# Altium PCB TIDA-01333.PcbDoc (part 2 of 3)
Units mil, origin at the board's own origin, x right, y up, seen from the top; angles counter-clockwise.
Board outline 6250 x 2150 mil, 4 copper layers (Top Layer, GND, VDD, Bottom Layer), stack 61.6 mil thick; 242 components, 144 nets, 711 pads, 252 vias.
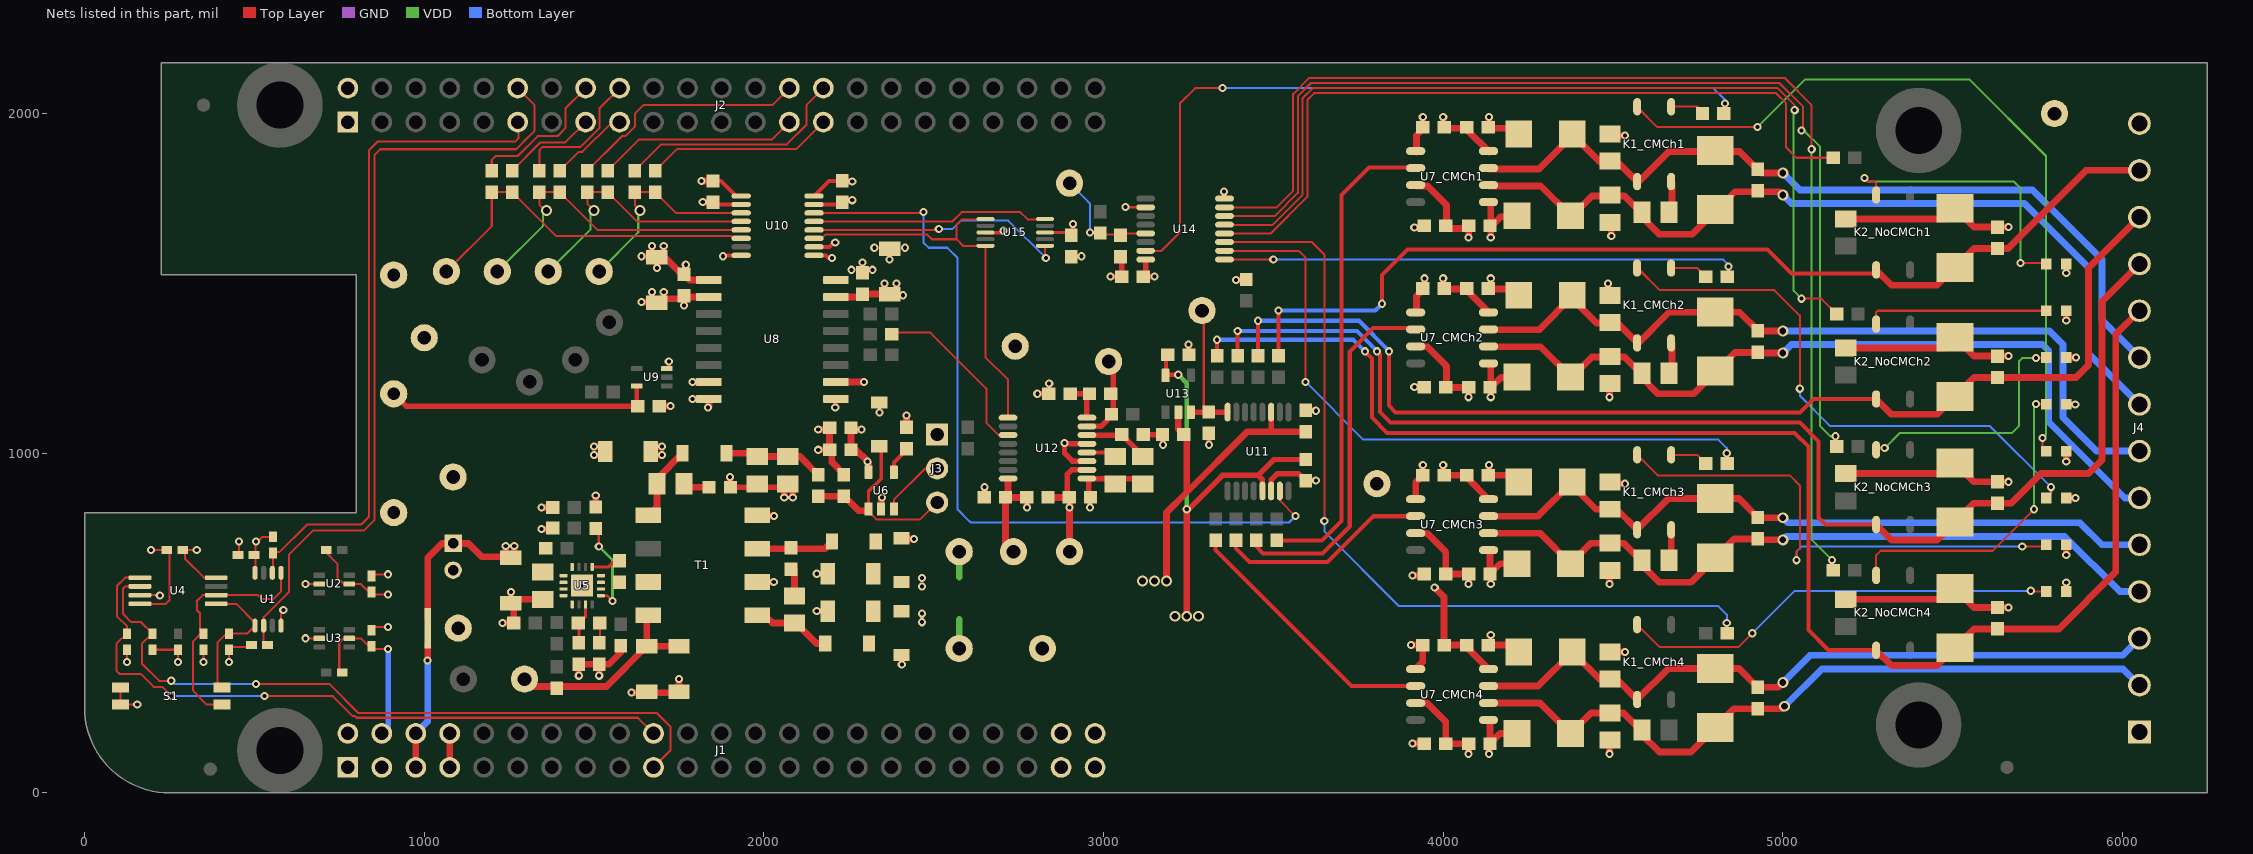
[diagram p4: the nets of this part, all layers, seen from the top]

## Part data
C1 C2 C3 C4: "CAP, CERM, 0.1 µF, 50 V, +/- 10%, X7R, 0402"
C5: "CAP, CERM, 1000 pF, 2000 V, +/- 10%, X7R, 1206_190"
C6: "CAP, AL, 47 µF, 35 V, +/- 20%, TH"
C7 C13 C14 C33 C36: "CAP, CERM, 22 µF, 10 V, +/- 10%, X7R, 1206"
C8 C18 C19 C49 C50: "CAP, CERM, 10 µF, 10 V, +/- 10%, X7R, 0805"
C9 C12: "CAP, CERM, 2.2 µF, 50 V, +/- 10%, X7R, 1206"
C10 C17 C25_CMCh1 C25_CMCh2 C25_CMCh3 C25_CMCh4 C30_CMCh1 C30_CMCh2 C30_CMCh3 C30_CMCh4 C34 C35 C37 C38 C39 C40 C43 C46 C47 C51 C52 C53: "CAP, CERM, 0.1 µF, 50 V, +/- 10%, X7R, 0603"
C11 C23: "CAP, CERM, 15 pF, 50 V, +/- 5%, C0G/NP0, 0603"
C15 C16 C21: "CAP, CERM, 2.2 µF, 10 V, +/- 10%, X7R, 0603"
C20: "CAP, CERM, 0.033 µF, 50 V, +/- 10%, X7R, 0603"
C22: "CAP, CERM, 82 pF, 50 V, +/- 5%, C0G/NP0, 0603"
C24 C28_CMCh1 C28_CMCh2 C28_CMCh3 C28_CMCh4 C32_NoCMCh1 C32_NoCMCh2 C32_NoCMCh3 C32_NoCMCh4: "CAP, CERM, 0.01 µF, 100 V, +/- 10%, X7R, 0603"
C26_CMCh1 C26_CMCh2 C26_CMCh3 C26_CMCh4 C31_CMCh1 C31_CMCh2 C31_CMCh3 C31_CMCh4 C41 C42 C48: "CAP, CERM, 1 µF, 16 V, +/- 10%, X7R, 0603"
C27_CMCh1 C27_CMCh2 C27_CMCh3 C27_CMCh4 C29_CMCh1 C29_CMCh2 C29_CMCh3 C29_CMCh4: "CAP, CERM, 1000 pF, 630 V, +/- 5%, X7R, 0805"
C44: "CAP, CERM, 100 pF, 50 V, +/- 5%, C0G/NP0, 0603"
C45: "CAP, CERM, 820 pF, 50 V, +/- 5%, C0G/NP0, 0603"
D1 D4: "Diode, Schottky, 100 V, 0.2 A, SOD-123"
D2 D3: "Diode, Zener, 16 V, 500 mW, SOD-123"
D5 D6: "Diode, Schottky, 30 V, 0.5 A, SOD-123"
D7_CMCh1 D7_CMCh2 D7_CMCh3 D7_CMCh4 D10_CMCh1 D10_CMCh2 D10_CMCh3 D10_CMCh4: "Diode, TVS, Bi, 160 V, 400 W, SMA"
D8_CMCh1 D8_CMCh2 D8_CMCh3 D8_CMCh4 D11_NoCMCh1 D11_NoCMCh2 D11_NoCMCh3 D11_NoCMCh4: "LED, Blue, SMD"
D9_CMCh1 D9_CMCh2 D9_CMCh3 D9_CMCh4 D12_NoCMCh1 D12_NoCMCh2 D12_NoCMCh3 D12_NoCMCh4: "Diode, TVS, Bi, 36 V, 600 W, SMB"
FID1 FID2 FID3: "Fiducial mark.  There is nothing to buy or mount."
J1 J2: "Female Connector, 2.54mm, 23x2, TH"
J3: "Header, 100mil, 3x1, Tin, TH"
J4: "Header (Shrouded), 3.5mm, 14x1, Tin, R/A, TH"
K1_CMCh1 K1_CMCh2 K1_CMCh3 K1_CMCh4 K2_NoCMCh1 K2_NoCMCh2 K2_NoCMCh3 K2_NoCMCh4: "Relay, SPST-NO (1 Form A), 0.1 A, 1.2 VDC, SMD"
Logo1: library part Pb-Free
Logo2: library part FCC_disclaimer, "FCC_disclaimer"
MH1 MH2 MH3 MH4: library part "Mounting Hole (Imperial) with Pads", "PCB Mounting Hole"
NT1: "Single point connection between nets."
R1 R2 R3 R4 R13 R14 R15: "RES, 47 k, 5%, 0.063 W, 0402"
R5 R6 R7 R8 R9 R10 R11 R12 R25 R38 R46: "RES, 0, 5%, 0.1 W, 0603"
R16 R17: "RES, 6.65 k, 1%, 0.063 W, 0402"
R18 R27: "RES, 1.0 k, 5%, 0.125 W, 0805"
R19 R28: "RES, 10 k, 5%, 0.1 W, 0603"
R20: "RES, 220 k, 5%, 0.1 W, 0603"
R21: "RES, 16.2 k, 1%, 0.1 W, 0603"
R22 R33 R34 R35 R36 R49: "RES, 49.9, 1%, 0.1 W, 0603"
R23: "RES, 75 k, 5%, 0.1 W, 0603"
R24: "RES, 10.0 k, 1%, 0.1 W, 0603"
R26: "RES, 240 k, 5%, 0.1 W, 0603"
R29_CMCh1 R29_CMCh2 R29_CMCh3 R29_CMCh4 R31_NoCMCh1 R31_NoCMCh2 R31_NoCMCh3 R31_NoCMCh4: "RES, 180, 5%, 0.1 W, 0603"
R30_CMCh1 R30_CMCh2 R30_CMCh3 R30_CMCh4 R32_NoCMCh1 R32_NoCMCh2 R32_NoCMCh3 R32_NoCMCh4: "RES, 200, 0.1%, 0.125 W, 0805"
R37 R39 R40 R41 R42 R43 R44 R45: "RES, 5.11 k, 1%, 0.1 W, 0603"
R47: "RES, 374, 1%, 0.1 W, 0603"
R48: "RES, 100 k, 5%, 0.1 W, 0603"
R50: "RES, 47 k, 5%, 0.1 W, 0603"
S1: "Switch, SPST, Off-On, 2 Pos, SMD"
SH-J1: "Shunt, 2.54mm, Gold, Black"
T1: "Transformer, 2.7 uH, SMT"
TP1 TP2 TP3: "TEST POINT.  No entry in BOM."
TP4 TP5 TP7 TP10: "Test Point, Miniature, Red, TH"
TP6 TP11 TP12 TP13 TP14 TP26: "Test Point, Miniature, Black, TH"
TP8: "Test Point, Miniature, White, TH"
TP9 TP15 TP16 TP17 TP18 TP19 TP20 TP21 TP22 TP24 TP25 TP27: "Test Point, Miniature, Yellow, TH"
TP23: "Test Point, Miniature, Orange, TH"
U1: "Dual 2-Input Exclusive-OR Gate, DCT0008A"
U2 U3: "Single 3-Input Positive-OR Gate, DCK0006A"
U4: "256K I2C CMOS Serial EEPROM, TSSOP-8"
U5: "2.95V To 6V Input, 2W, Isolated DC/DC Converter with Integrated FETs, RTE0016F (WQFN-16)"
U6: "150-mA Low-noise Low-dropout Regulator With Shutdown, DBV0005A"
U7_CMCh1 U7_CMCh2 U7_CMCh3 U7_CMCh4: "High Common-Mode Voltage Difference Amplifier, D0008A"
U8: "ISOW7841DW, DW0016B"
U9: "Single Power Supply Single Buffer Gate with 3-State Output CMOS Logic Level Shifter, DCK0005A"
U10: "4242-VPK Small-Footprint and Low-Power Quad Channels Digital Isolators, DBQ0016A"
U11: "MUX36xxx 36-V, Low-Capacitance, Low-Leakage-Current, Precision, Analog Multiplexers, PW0016A (TSSOP-16)"
U12: "16-bit, 1 MSPS, 5V SAR ADC with Integrated Analog Front End & Bipolar Inputs, PW0016A (TSSOP-16)"
U13: "36-V, Precision, Rail-to-Rail Input/Output, Low Offset Voltage, Low Input Bias Current Op Amp with e-trim, DBV0005A"
U14: "8-Bit Shift Register With Output Registers, PW0016A"
U15: "DUAL 10-Ohm SPDT ANALOG SWITCH, DGS0010A"
ZZ1 ZZ2 ZZ3: library part AssemblyNote

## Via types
v1: diameter 24, hole 12, Top Layer to Bottom Layer, 210 vias
v2: diameter 39.37, hole 19.68, Top Layer to Bottom Layer, 24 vias
v3: diameter 32, hole 20, Top Layer to Bottom Layer, 17 vias
v4: diameter 19.68, hole 7.87, Top Layer to Bottom Layer, 1 vias

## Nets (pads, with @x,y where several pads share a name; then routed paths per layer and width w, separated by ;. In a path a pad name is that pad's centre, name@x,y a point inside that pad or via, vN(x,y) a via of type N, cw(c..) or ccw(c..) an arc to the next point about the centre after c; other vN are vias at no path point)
+5V: C6.1 C7.1 C8.2 C33.1 C34.1 C38.1 NT1.2 R19.2 R20.2 TP4.1 U5.1 U5.2 U5.16 U8.1 U8.7 U10.1 | length 1038.5
  Top Layer w12: C38.1@1850.32,1801.5 1873.5,1801.5 1917.5,1757.5 U10.1@1933.03,1757.5
  Top Layer w20: NT1.2@1010,515 1010,692.01 1052.36,734.37 C6.1@1085,734.37 1130.63,734.37 1170,695 1240,695 1239.87,695.13 v1(1239.87,726.38) ; v1(1264.87,726.38) 1264.87,700.13 C7.1@1265,700 ; v1(1344.87,776.38) R19.2@1373.78,776.38 ; v1(1640,1580) C33.1@1670,1580 ; v1(1670,1610) C33.1@1670,1580 ; v1(1685,1545) C33.1@1685,1575 ; C33.1@1705,1590 v1(1705,1610) ; C34.1@1758.5,1526.5 1700,1585 1695,1580 C33.1@1670,1580 ; C34.1@1765,1526.5 1781.5,1510 U8.1@1837.99,1510 ; C34.1@1770,1531.5 v1(1770,1555) ; v1(1790,1210) U8.7@1837.99,1210 ; v1(1816.5,1801.5) C38.1@1850.32,1801.5
+5V_ISO: C15.1 C16.1 C35.1 C36.1 C39.1 C41.1 C51.1 C52.1 D5.2 R38.1 R48.2 TP10.1 U6.5 U8.10 U8.16 U10.10 U10.16 U12.16 U14.10 U14.16 U15.8 | length 1082.9
  Top Layer w8: U15.8@2827.6,1650 2896.5,1650 C51.1@2905,1641.5 ; v1(3065,1725) 3066.02,1723.98 U14.10@3123.86,1723.98
  Top Layer w12: U10.10@2147.6,1607.5 2192.5,1607.5 2205,1620 v1(2210,1620) ; U10.16@2147.6,1757.5 2191.91,1801.81 C39.1@2230.32,1801.81
  Top Layer w16: C51.1@2905,1641.5 2910,1646.5 2905,1651.5 2910,1656.5 v1(2910,1675) ; U14.16@3123.86,1570.43 3123.86,1527.36 C52.1@3116.5,1520 v1(3150,1520)
  Top Layer w20: U8.10@2212.01,1210 v1(2295,1210) ; C39.1@2232.13,1800 v1(2260,1800) ; C16.1@2256.5,1071.32 2256.5,1011.32 2270.33,1011.32 2305,976.65 v1(2305,975) 2307.91,972.09 U6.5@2307.91,944.13 ; C16.1@2257.8,1070.02 v1(2287.4,1070.02) ; C41.1@2711.5,865 2711.5,733.5 TP10.1@2735,710 ; C41.1@2718.86,872.36 U12.16@2718.86,924.29 ; C41.1@2718.86,877.36 C41.1@2711.5,870 R38.1@2773.5,870 2775,868.5 v1(2775,840) ; v1(3390,1510) 3418.5,1510 R48.2@3420,1511.5
  other v1: 2340,1119.86 2258.27,1540 2320,1540 2290,1561.02 2370,1570 2325,1605 2415,1605
+5V_JACK: J1.5 J1.6 NT1.1 | length 379.5
  Top Layer w20: J1.5@975,75 J1.6@975,175 ; v1(1010,390) NT1.1@1010,440
  Bottom Layer w20: J1.6@975,175 1010,210 v1(1010,390)
+5V_JACK_USB: J1.7 J1.8 | length 100
  Top Layer w20: J1.7@1075,75 J1.8@1075,175
+15V_ISO: C9.1 C30_CMCh1.1 C30_CMCh2.1 C30_CMCh3.1 C30_CMCh4.1 C31_CMCh1.1 C31_CMCh2.1 C31_CMCh3.1 C31_CMCh4.1 C46.1 C47.1 D1.1 D2.1 TP5.1 U7_CMCh1.7 U7_CMCh2.7 U7_CMCh3.7 U7_CMCh4.7 U11.13 U13.5 | length 2447.9
  Top Layer w6: C30_CMCh4.1@4074.76,144.51 C30_CMCh4.1@4075,144.28
  Top Layer w12: C46.1@3181.5,1285 3184.47,1282.03 3184.47,1231.01 v1(3220,1231.01)
  Top Layer w16: v1(3245,835) 3250,835 3350,935 3455,935 ; U11.13@3467.8,888.86 3467.8,922.2 3455,935 ; C47.1@3595,981.5 3501.5,981.5 3455,935
  Top Layer w20: v3(3245,520) v1(3245,835) ; U7_CMCh4.7@3918.98,264.51 3951.75,264.51 4007.76,208.5 C31_CMCh4.1@4007.76,144.51 C30_CMCh4.1@4074.76,144.51 ; U7_CMCh3.7@3918.98,764.51 3951.75,764.51 4007.76,708.5 C31_CMCh3.1@4007.76,644.51 C30_CMCh3.1@4074.76,644.51 ; U7_CMCh2.7@3921.2,1313.23 3953.97,1313.23 4009.98,1257.22 4009.98,1193.23 C30_CMCh2.1@4076.98,1193.23 ; U7_CMCh1.7@3921.2,1786.5 3953.97,1786.5 4009.98,1730.49 C31_CMCh1.1@4009.98,1666.5 ; C31_CMCh1.1@4009.98,1661.5 C30_CMCh1.1@4076.98,1661.5 ; v1(4075,115) C30_CMCh4.1@4075,144.28 ; v1(4075,615) C30_CMCh3.1@4075,644.28 ; v1(4075,1165) 4075,1185.21 C30_CMCh2.1@4080,1190.21 ; v1(4075,1635) 4075,1658.48 C30_CMCh1.1@4080,1663.48
  VDD w12: v1(3220,1231.01) 3245,1206 v1(3245,835)
  VDD w20: TP5.1@2575,425 2575,510
  other v1: 2465.98,502.52 2465.98,527.52
  other v3: 3210,520 3280,520
-15V_ISO: C12.2 C25_CMCh1.2 C25_CMCh2.2 C25_CMCh3.2 C25_CMCh4.2 C26_CMCh1.2 C26_CMCh2.2 C26_CMCh3.2 C26_CMCh4.2 C40.2 C43.2 D3.2 D4.2 TP7.1 U7_CMCh1.4 U7_CMCh2.4 U7_CMCh3.4 U7_CMCh4.4 U11.3 U13.2 | length 2039.9
  Top Layer w6: C25_CMCh2.2@4000,1489.69 C25_CMCh2.2@4004.98,1484.72 ; C25_CMCh1.2@4000.5,1962.46 4005.98,1956.99 C25_CMCh1.2@4008.48,1954.48
  Top Layer w16: v3(3150,623.78) v3@3155,623.78 ; 3493.39,1066.61 U11.3@3493.39,1121.14
  Top Layer w20: v3(3185,623.78) 3185,825 3245,885 ; U13.2@3220,1120.87 3220,1071.5 C43.2@3236.5,1055 3245,1046.5 3245,885 ; C40.2@3600,1063.5 3423.5,1063.5 3245,885 ; v1(3975,605) 4002.76,577.24 C25_CMCh4.2@4002.76,435 C26_CMCh4.2@4069.76,435 4069.76,428.29 U7_CMCh4.4@4133.54,364.51 ; C25_CMCh3.2@4000,937.76 v1(4000,965) ; v1(4000,1515) 4000,1488.74 C25_CMCh2.2@4005,1483.74 ; C25_CMCh1.2@4000,1961.96 v1(4000,1990) ; C25_CMCh3.2@4002.76,935 C26_CMCh3.2@4069.76,935 4069.76,928.29 U7_CMCh3.4@4133.54,864.51 ; C25_CMCh2.2@4004.98,1483.72 4071.98,1483.72 4071.98,1477.01 U7_CMCh2.4@4135.76,1413.23 ; C25_CMCh1.2@4004.98,1956.99 4005.98,1956.99 4071.98,1956.99 4071.98,1950.28 U7_CMCh1.4@4135.76,1886.5
  VDD w20: 2575,635 TP7.1@2575,710
  other v1: 2465.98,607.52 2465.98,632.52
  other v3: 3115,623.78
"A0 / SER": R7.2 R8.2 TP20.1 U10.5 | length 952.7
  Top Layer w6: v3(1360,1715) 1360,1710 1338.68,1731.32 R8.2@1338.68,1768.5 R7.2@1398.68,1768.5 1509.68,1657.5 U10.5@1933.03,1657.5
  VDD w6: TP20.1@1215,1535 1350,1670 1350,1705 v3(1360,1715)
"A0 / SER_ISO": U10.12 U15.6 | length 776
  Top Layer w6: U10.12@2147.6,1657.5 2512.5,1657.5 v1(2515,1660) ; U15.6@2827.6,1610.63 2827.6,1577.4 v1(2830,1575)
  Bottom Layer w6: v1(2515,1660) 2555,1660 2580,1685 2720,1685 v1(2830,1575)
"A1 / R\C\L\R\": R9.2 R10.2 TP21.1 U10.4 | length 786.4
  Top Layer w6: v3(1500,1715) 1480,1735 R10.2@1480,1768.5 R9.2@1540,1768.5 1626,1682.5 U10.4@1933.03,1682.5
  VDD w6: TP21.1@1365,1535 1490,1660 1490,1705 v3(1500,1715)
"A1 / R\C\L\R\_ISO": U10.13 U15.10 | length 699.4
  Top Layer w6: U10.13@2147.97,1682.87 2555.22,1682.87 2582.35,1710 2755,1710 2776.26,1688.74 U15.10@2827.28,1688.74
A2: R11.2 R12.2 TP22.1 U10.3 | length 627.7
  Top Layer w6: v3(1635,1715) 1620,1730 R12.2@1620,1768.5 R11.2@1680,1768.5 1741,1707.5 U10.3@1933.03,1707.5
  VDD w6: TP22.1@1515,1535 1630,1650 1630,1710 v3(1635,1715)
A2_ISO: U10.14 U11.15 | length 2383.9
  Top Layer w6: U10.14@2147.6,1707.5 2467.5,1707.5 v1(2470,1710) ; U11.15@3518.98,888.86 3518.98,861.02 v1(3565,815)
  Bottom Layer w6: v1(2470,1710) 2470,1620 2485,1605 2540,1605 2570,1575 2570,835 2605,800 2605.38,800 2609.25,796.13 3546.13,796.13 v1(3565,815)
AVDD: C42.1 R38.2 TP23.1 U12.2 | length 349
  Top Layer w16: C42.1@2893.5,865 2893.5,938.5 2906.02,951.02 U12.2@2951.14,951.02
  Top Layer w20: R38.2@2836.5,870 C42.1@2893.5,870 ; C42.1@2898.5,870 2900,868.5 v1(2900,840) ; TP23.1@2900,710 v1@2900,835
CAPE_A0: J2.12 R1.2 U1.2 | length 2336.2
  Top Layer w6: U1.2@527.22,473.95 527.22,517.22 562.25,552.25 562.53,552.25 596.28,586 596.28,586.28 602.02,592.02 602.02,702.02 672.13,772.13 821.9,772.13 852.87,803.1 852.87,1877.87 870,1895 1270.5,1895 1292.87,1917.38 ; U1.2@527.2,492.24 527.2,446.42 R1.2@538.62,435 ; J2.12@1275,2075 1325,2025 1325,1950 1292.87,1917.87
CAPE_A1: J2.11 R3.2 U1.6 | length 1966.8
  Top Layer w6: U1.6@555,649.96 R3.2@555,706.38 557.2,708.58 573.58,708.58 655,790 814.5,790 837.2,812.71 837.2,1892.2 862.2,1917.2 1267.43,1917.2 1277.2,1926.98 J2.11@1277.2,1977.2
CH_IN+1: C32_NoCMCh1.1 D12_NoCMCh1.2 J4.13 K2_NoCMCh1.3 R45.2 | length 2975.3
  Top Layer w12: R45.2@3515,1292.07 v1(3515,1420) ; v1(3820,1440) 3820,1525 3895,1600 4955,1600 5025.24,1529.76 K2_NoCMCh1.3@5275,1529.76
  Top Layer w20: K2_NoCMCh1.3@5275,1539.76 5320.21,1494.55 5454.24,1494.55 D12_NoCMCh1.2@5507,1547.31 5562.51,1602.82 C32_NoCMCh1.1@5632,1602.82 5662.82,1602.82 5892.87,1832.87 J4.13@6050.04,1832.87
  Bottom Layer w12: v1(3515,1420) 3800,1420 v1(3820,1440)
CH_IN+2: C32_NoCMCh2.1 D12_NoCMCh2.2 J4.12 K2_NoCMCh2.3 R44.2 | length 3342.1
  Top Layer w12: R44.2@3455,1292.07 v1(3455,1390) ; v1(3840,1300) 3840,1140 3860,1120 5050,1120 5089.76,1159.76 K2_NoCMCh2.3@5275,1159.76
  Top Layer w20: K2_NoCMCh2.3@5275,1159.76 5320.21,1114.55 5454.24,1114.55 D12_NoCMCh2.2@5507,1167.31 5562.51,1222.82 C32_NoCMCh2.1@5632,1222.82 5862.82,1222.82 5900,1260 5900,1545.04 J4.12@6050.04,1695.08
  Bottom Layer w12: v1(3455,1390) 3751.59,1390 3840,1301.59 v1(3840,1300)
CH_IN+3: C32_NoCMCh3.1 D12_NoCMCh3.2 J4.11 K2_NoCMCh3.3 R43.2 | length 3820.6
  Top Layer w12: R43.2@3395,1292.07 v1(3395,1360) ; v1(3805,1300) 3814.13,1290.87 3814.13,1120.87 3845,1090 5050,1090 5105,1035 5105,810 5125.24,789.76 K2_NoCMCh3.3@5275,789.76
  Top Layer w20: K2_NoCMCh3.3@5275,789.76 5320.21,744.55 5454.24,744.55 D12_NoCMCh3.2@5507,797.31 5562.51,852.82 C32_NoCMCh3.1@5632,852.82 5672.82,852.82 5760,940 5900,940 5940,980 5940,1447.24 J4.11@6050.04,1557.28
  Bottom Layer w12: v1(3395,1360) 3746.59,1360 3805,1301.59 v1(3805,1300)
CH_IN+4: C32_NoCMCh4.1 D12_NoCMCh4.2 J4.10 K2_NoCMCh4.3 R42.2 | length 4414.3
  Top Layer w12: R42.2@3334.02,1293.05 v1(3334.02,1334.02) ; v1@3770,1298.41 3790,1278.41 3790,1105 3835,1060 3850,1060 5034.87,1060.13 5075,1020 5075,480 5135.24,419.76 K2_NoCMCh4.3@5275,419.76
  Top Layer w20: K2_NoCMCh4.3@5275,419.76 5320.21,374.55 5454.24,374.55 D12_NoCMCh4.2@5507,427.31 5562.51,482.82 C32_NoCMCh4.1@5632,482.82 5812.82,482.82 5980,650 5980,1349.45 J4.10@6050.04,1419.49
  Bottom Layer w12: v1(3334.02,1334.02) 3735.98,1334.02 v1(3770,1300)
CH_V/C_SWITCH1: R31_NoCMCh1.2 U14.4 | length 2285.3
  Top Layer w6: U14.4@3356.14,1646.89 3491.89,1646.89 3600,1755 3600,2040 3620,2060 4980,2060 5010,2030 5010,1900 5040,1870 R31_NoCMCh1.2@5148.5,1870
CH_V/C_SWITCH2: R31_NoCMCh2.2 U14.5 | length 2735.8
  Top Layer w6: U14.5@3356.14,1672.48 3497.86,1672.48 3586.13,1760.75 3586.13,2045.75 3615.38,2075 4984.62,2075 5035,2024.62 v1(5035,2010) ; v1(5055,1455) 5113.5,1455 R31_NoCMCh2.2@5158.5,1410
  VDD w6: v1(5035,2010) 5032.13,2007.13 5032.13,1477.87 v1(5055,1455)
CH_V/C_SWITCH3: R31_NoCMCh3.2 U14.6 | length 3114.7
  Top Layer w6: U14.6@3356.14,1698.07 3503.83,1698.07 3572.25,1766.49 3572.25,2051.49 3610.76,2090 4989.62,2090 5059.62,2020 5059.62,1954.62 v1(5055,1950) ; R31_NoCMCh3.2@5155,1023.5 v1(5155,1050)
  VDD w6: v1(5055,1950) 5062.35,1950 5110,1902.35 5110,1080 5140,1050 v1(5155,1050)
CH_V/C_SWITCH4: R31_NoCMCh4.2 U14.7 | length 3483.2
  Top Layer w6: U14.7@3356.14,1723.66 3509.8,1723.66 3558.38,1772.24 3558.38,2057.24 3606.14,2105 5005,2105 5085,2025 v1(5085,1895) ; v1(5145,685) 5145,658.5 R31_NoCMCh4.2@5148.5,655
  VDD w6: v1(5085,1895) 5085,745 v1(5145,685)
CMCH_IN+1: C27_CMCh1.1 C28_CMCh1.1 D7_CMCh1.1 D9_CMCh1.2 J4.9 K1_CMCh1.3 U7_CMCh1.3 | length 2407.6
  Top Layer w20: U7_CMCh1.3@4135.76,1836.5 4281.73,1836.5 4382.22,1936.99 4462.22,1856.99 4493.48,1856.99 4513.24,1856.99 4573.48,1796.75 4665,1888.27 4803.48,1888.27 4872.97,1888.27 4928.48,1832.76 4936.24,1825 v3(5000,1825)
  Bottom Layer w20: v3(5000,1825) 5050,1775 5735,1775 5940,1570 5940,1391.73 J4.9@6050.04,1281.69
CMCH_IN+2: C27_CMCh2.1 C28_CMCh2.1 D7_CMCh2.1 D9_CMCh2.2 J4.7 K1_CMCh2.3 U7_CMCh2.3 | length 2353.3
  Top Layer w20: U7_CMCh2.3@4135.76,1363.23 4281.73,1363.23 4382.22,1463.72 4382.22,1452.78 4451.28,1383.72 4493.48,1383.72 4513.24,1383.72 4573.48,1323.48 4665,1415 4803.48,1415 4872.97,1415 C28_CMCh2.1@4928.48,1359.49 ; C28_CMCh2.1@4928.99,1360 v3(5000,1360)
  Bottom Layer w20: v3(5000,1360) 5785,1360 5825,1320 5825,1105 5923.9,1006.1 J4.7@6050.04,1006.1
CMCH_IN+3: C27_CMCh3.1 C28_CMCh3.1 D7_CMCh3.1 D9_CMCh3.2 J4.5 K1_CMCh3.3 U7_CMCh3.3 | length 2116.2
  Top Layer w20: U7_CMCh3.3@4133.54,814.51 4279.51,814.51 D7_CMCh3.1@4380,915 4380,905 4450,835 C27_CMCh3.1@4491.26,835 4511.02,835 K1_CMCh3.3@4571.26,774.76 4662.78,866.28 D9_CMCh3.2@4801.26,866.28 4870.75,866.28 C28_CMCh3.1@4926.26,810.77 4927.03,810 v3(5000,810)
  Bottom Layer w20: v3(5000,810) 5015,795 5875,795 5939.49,730.51 J4.5@6050.04,730.51
CMCH_IN+4: C27_CMCh4.1 C28_CMCh4.1 D7_CMCh4.1 D9_CMCh4.2 J4.3 K1_CMCh4.3 U7_CMCh4.3 | length 2143.4
  Top Layer w20: U7_CMCh4.3@4133.54,314.51 4279.51,314.51 D7_CMCh4.1@4380,415 4460,335 C27_CMCh4.1@4491.26,335 4511.02,335 K1_CMCh4.3@4571.26,274.76 4662.78,366.28 D9_CMCh4.2@4801.26,366.28 4870.75,366.28 C28_CMCh4.1@4926.26,310.77 4985.77,310.77 v3(5000,325) v3@5006.54,325
  Bottom Layer w20: v3(5000,325) 5080,405 6000.12,405 J4.3@6050.04,454.92
CMCH_IN-1: C28_CMCh1.2 C29_CMCh1.2 D9_CMCh1.1 D10_CMCh1.1 J4.8 R30_CMCh1.1 U7_CMCh1.2 | length 2487.8
  Top Layer w20: U7_CMCh1.2@4135.76,1786.5 4287.22,1786.5 4377.22,1696.5 4437.71,1756.99 4493.48,1756.99 4533.48,1756.99 4583.48,1706.99 4583.48,1696.99 4635.47,1645 4734.22,1645 4803.48,1714.26 4858.99,1769.77 4928.48,1769.77 4990.23,1769.77 v3(5000,1760)
  Bottom Layer w20: v3(5000,1760) 5025,1735 5711.65,1735 5900,1546.65 5900,1293.94 J4.8@6050.04,1143.9
CMCH_IN-2: C28_CMCh2.2 C29_CMCh2.2 D9_CMCh2.1 D10_CMCh2.1 J4.6 R30_CMCh2.1 U7_CMCh2.2 | length 2398.9
  Top Layer w20: U7_CMCh2.2@4135.76,1313.23 4287.22,1313.23 4377.22,1223.23 4437.71,1283.72 4493.48,1283.72 4533.48,1283.72 4583.48,1233.72 4583.48,1223.72 4632.2,1175 4737.5,1175 4803.48,1240.98 4858.99,1296.5 4928.48,1296.5 4929.98,1295 v3(5000,1295)
  Bottom Layer w20: v3(5000,1295) 5025,1320 5765,1320 5782.39,1302.61 5782.39,1092.61 6006.69,868.31 J4.6@6050.04,868.31
CMCH_IN-3: C28_CMCh3.2 C29_CMCh3.2 D9_CMCh3.1 D10_CMCh3.1 J4.4 R30_CMCh3.1 U7_CMCh3.2 | length 2157.8
  Top Layer w20: U7_CMCh3.2@4133.54,764.51 4285,764.51 D10_CMCh3.1@4375,674.51 4435.49,735 C29_CMCh3.2@4491.26,735 4531.26,735 4581.26,685 4581.26,675 4636.26,620 4728.99,620 D9_CMCh3.1@4801.26,692.27 4856.77,747.78 C28_CMCh3.2@4926.26,747.78 4929.04,745 v3(5000,745)
  Bottom Layer w20: v3(5000,745) 5010,755 5830,755 5992.28,592.72 J4.4@6050.04,592.72
CMCH_IN-4: C28_CMCh4.2 C29_CMCh4.2 D9_CMCh4.1 D10_CMCh4.1 J4.2 R30_CMCh4.1 U7_CMCh4.2 | length 2153.6
  Top Layer w20: U7_CMCh4.2@4133.54,264.51 4285,264.51 D10_CMCh4.1@4375,174.51 4435.49,235 C29_CMCh4.2@4491.26,235 4531.26,235 4581.26,185 4581.26,175 4636.26,120 4728.99,120 D9_CMCh4.1@4801.26,192.27 4856.77,247.78 C28_CMCh4.2@4926.26,247.78 4997.78,247.78 v3(5005,255)
  Bottom Layer w20: v3(5005,255) 5115,365 6002.17,365 J4.2@6050.04,317.13
CMCH_OUT1: R41.2 U7_CMCh1.6 | length 1428.4
  Top Layer w12: R41.2@3510,743.5 3643.5,743.5 3700,800 3700,1760 3781.5,1841.5 U7_CMCh1.6@3921.2,1841.5
CMCH_OUT2: R40.2 U7_CMCh2.6 | length 1074.4
  Top Layer w12: R40.2@3450,743.5 3450,725 3470,705 3645,705 3725,785 3725,1300 3793.23,1368.23 U7_CMCh2.6@3921.2,1368.23
CMCH_OUT3: R39.2 U7_CMCh3.6 | length 624.8
  Top Layer w12: R39.2@3390,743.5 3390,720 3430,680 3660,680 3794.51,814.51 U7_CMCh3.6@3918.98,814.51
CMCH_OUT4: R37.2 U7_CMCh4.6 | length 783.4
  Top Layer w12: R37.2@3330,743.5 3330,715 3730.49,314.51 U7_CMCh4.6@3918.98,314.51
CMCH_V/C_SWITCH1: R29_CMCh1.2 U14.15 | length 2182.4
  Top Layer w6: U14.15@3123.86,1595.71 3170.71,1595.71 3225,1650 3225,2030 3270,2075 v1(3350,2075) ; v1(4830,2030) 4830,2001.5 R29_CMCh1.2@4831.5,2000
  Bottom Layer w6: v1(3350,2075) 4795,2075 4830,2040 v1(4830,2030)
CMCH_V/C_SWITCH2: R29_CMCh2.2 U14.1 | length 1526.4
  Top Layer w6: U14.1@3356.14,1570.12 v1(3499.88,1570.12) ; R29_CMCh2.2@4836.5,1520 4840,1523.5 v1(4840,1550)
  Bottom Layer w6: v1@3500,1570 4825,1570 4840,1555 v1(4840,1550)
CMCH_V/C_SWITCH3: R29_CMCh3.2 U14.2 | length 1978.8
  Top Layer w6: U14.2@3356.14,1595.71 3574.29,1595.71 3595,1575 v1(3595,1210) ; v1(4835,1000) 4836.5,998.5 R29_CMCh3.2@4836.5,970
  Bottom Layer w6: v1(3595,1210) 3765,1040 4810,1040 4835,1015 v1(4835,1000)
CMCH_V/C_SWITCH4: R29_CMCh4.2 U14.3 | length 2466
  Top Layer w6: U14.3@3356.14,1621.3 3613.7,1621.3 3650,1585 v1(3650,800) ; v1(4835,500) 4836.5,498.5 R29_CMCh4.2@4836.5,470
  Bottom Layer w6: v1(3650,800) 3650,770 3870,550 4810,550 4835,525 v1(4835,500)
CONVST/C\S\_ISO: R34.2 U12.11 | length 525.7
  Top Layer w6: R34.2@2376.5,1355 2490,1355 2655,1190 2655,1090.26 2691.87,1053.39 U12.11@2718.86,1053.39
DGND: C1.2 C2.2 C3.2 C4.2 C5.2 C6.2 C7.2 C8.1 C13.2 C14.2 C17.2 C22.1 C33.2 C34.2 C37.2 C38.2 J1.1 J1.2 J1.43 J1.44 J1.45 J1.46 J2.1 J2.2 R23.1 R24.1 R26.1 R28.1 S1.1 S1.2 TP2.1 TP3.1 TP6.1 TP11.1 U1.4 U2.2 U3.2 U4.4 U4.7 U5.3 U5.4 U5.5 U5.17@1465,610 U8.2 U8.8 U9.3 U10.2 U10.8 | length 1874.9
  Top Layer w6: S1.1@105,310 S1.2@105,260 v1(155,260) v1@160.03,260 ; U4.7@162.8,582.2 212.2,582.2 220,590 221.35,588.65 v1(221.35,581.35) ; C4.2@288.62,715 295,708.65 295,690 351.61,633.39 U4.4@387.2,633.39 ; C4.2@296.53,715 v1(330,715) ; C1.2@455,693.62 v1(455,740) ; U1.4@578.39,492.37 578.39,528.51 585,535.13 v1(585,538.17) ; v1(649.98,614.99) U2.2@690.71,615 ; v1(650.73,455.01) U3.2@691.45,455.02 ; C3.2@845,478.64 854.9,488.52 v1(893.52,488.52) ; C2.2@845,638.62 849.9,643.52 v1@888.25,643.52 ; C22.1@1449.73,376.38 1454.73,381.38 C22.1@1456.11,380
  Top Layer w12: U9.3@1714.29,1249.27 1720,1254.98 v1(1720,1270) ; C38.2@1866.32,1732.5 U10.2@1933.03,1732.5 ; v1(1880,1580) 1882.5,1582.5 U10.8@1933.03,1582.5
  Top Layer w20: v1(1230,500) R24.1@1263.5,500 1263.5,561.89 1254.87,570.52 v1(1254.87,591.38) ; C7.2@1256.81,570 C8.1@1348.9,570 ; v1(1345,840) R23.1@1378.5,840 ; v1(1455,345) C22.1@1455,378.5 ; C22.1@1457.25,378.86 1544.65,378.86 1578.55,412.76 R26.1@1578.55,433.31 ; v1(1500,995) C5.2@1523.07,995 ; v1(1500,1020) C5.2@1518.07,1020 ; C17.2@1504.87,845.52 1505,845.65 v1(1505,875) ; C17.2@1507.4,840 C17.2@1508.9,841.5 ; v1(1515,345) R28.1@1515,378.5 ; v1(1610,295) 1746.93,295 C14.2@1750,298.07 v1(1750,335) ; v1(1640,1445) C33.2@1663.07,1445 ; C33.2@1670,1451.93 v1(1670,1475) ; C37.2@1691.5,1138.68 v1(1725,1138.68) ; C33.2@1691.93,1455 C34.2@1765,1455 ; C33.2@1705,1451.93 v1(1705,1475) ; v1(1765,1435) C34.2@1765,1458.07 ; C34.2@1765,1463.5 1765,1460 U8.2@1837.99,1460 ; v1(1790,1160) U8.8@1837.99,1160 1837.99,1137.99 v1(1835,1135) ; v1(1820,1740) C38.2@1838.82,1740
  other v1: 893.52,643.52
  other v4: 1465,610
DVDD: C1.1 C2.1 C3.1 C4.1 C37.1 J1.3 J1.4 R1.1 R2.1 R3.1 R4.1 R13.1 R14.1 R15.1 R16.1 R17.1 TP1.1 U1.8 U2.5 U3.5 U4.8 U9.5 | length 2316.5
  Top Layer w6: v1(125,385) R17.1@125.01,421.39 ; U4.8@162.8,556.61 238.86,556.61 249.87,567.63 249.87,715.01 C4.1@241.38,715 ; v1(195,715) C4.1@233.52,715.01 ; v1@275.01,377.89 R15.1@275.01,421.39 ; v1@350.02,377.89 R13.1@350.02,421.39 ; v1@425.02,377.89 R14.1@425.02,421.39 ; R14.1@425.02,429.27 477.77,429.27 R1.1@491.38,442.87 ; U1.8@503.62,649.89 503.62,733.62 523.62,753.62 R3.1@555,753.62 ; R2.1@703.52,715.01 745,673.53 745,633.25 749.69,628.57 758.38,619.84 763.24,615.01 813.52,615.01 845.02,583.52 v1(893.52,583.52) v1@895.02,585.01 ; R4.1@758.62,355 749.7,363.92 749.7,441.48 763.24,455.02 U3.5@779.31,455.02 813.52,455.02 845.02,423.52 v1(893.52,423.52)
  Top Layer w8: R16.1@200.01,421.39 R15.1@275.01,421.39
  Top Layer w12: U9.5@1625.71,1198.09 1625.71,1141.48 C37.1@1628.5,1138.68
  Top Layer w16: TP1.1@910,1175 946.32,1138.68 C37.1@1628.5,1138.68
  Bottom Layer w16: J1.4@875,175 893.52,193.52 v1(893.52,423.52)
  other v1: 275,385 350,385 425,385 505,740
GND_ISO: C5.1 C9.2 C12.1 C15.2 C16.2 C18.2 C19.1 C21.2 C23.2 C24.2 C25_CMCh1.1 C25_CMCh2.1 C25_CMCh3.1 C25_CMCh4.1 C26_CMCh1.1 C26_CMCh2.1 C26_CMCh3.1 C26_CMCh4.1 C27_CMCh1.2 C27_CMCh2.2 C27_CMCh3.2 C27_CMCh4.2 C29_CMCh1.1 C29_CMCh2.1 C29_CMCh3.1 C29_CMCh4.1 C30_CMCh1.2 C30_CMCh2.2 C30_CMCh3.2 C30_CMCh4.2 C31_CMCh1.2 C31_CMCh2.2 C31_CMCh3.2 C31_CMCh4.2 C32_NoCMCh1.2 C32_NoCMCh2.2 C32_NoCMCh3.2 C32_NoCMCh4.2 C35.2 C36.2 C39.2 C40.1 C41.2 C42.2 C43.1 C45.2 C46.2 C47.2 C48.2 C49.1 C50.1 C51.2 C52.2 C53.2 D2.2 D3.1 D7_CMCh1.2 D7_CMCh2.2 D7_CMCh3.2 D7_CMCh4.2 D8_CMCh1.2 D8_CMCh2.2 D8_CMCh3.2 D8_CMCh4.2 D10_CMCh1.2 D10_CMCh2.2 D10_CMCh3.2 D10_CMCh4.2 D11_NoCMCh1.2 D11_NoCMCh2.2 D11_NoCMCh3.2 D11_NoCMCh4.2 D12_NoCMCh1.1 D12_NoCMCh2.1 D12_NoCMCh3.1 D12_NoCMCh4.1 J3.1 J4.1 J4.14 R32_NoCMCh1.1 R32_NoCMCh2.1 R32_NoCMCh3.1 R32_NoCMCh4.1 R47.2 T1.5 T1.7 TP12.1 TP13.1 TP14.1 TP26.1 U6.2 U7_CMCh1.1 U7_CMCh1.5 U7_CMCh2.1 U7_CMCh2.5 U7_CMCh3.1 U7_CMCh3.5 U7_CMCh4.1 U7_CMCh4.5 U8.9 U8.15 U10.9 U10.15 U11.14 U12.1 U12.3 U12.5 U14.8 U15.3 | length 6684.6
  Top Layer w6: C16.2@2184.47,1070.02 C16.2@2187.93,1066.56 ; U6.2@2345.63,830.87 U6.2@2347.72,832.95 ; C25_CMCh1.1@3940,1958.97 C25_CMCh1.1@3941.98,1956.99 ; C26_CMCh4.1@4132.76,435 C26_CMCh4.1@4136.26,438.5 ; C26_CMCh3.1@4132.76,935 C26_CMCh3.1@4135,937.24 ; C30_CMCh4.2@4135,141.76 C30_CMCh4.2@4137.76,144.51 ; C26_CMCh2.1@4134.98,1483.72 C26_CMCh2.1@4138.48,1487.22
  Top Layer w10: U15.3@2652.09,1649.37 2699.37,1649.37 v1(2705,1655)
  Top Layer w12: U10.9@2147.6,1582.5 2182.5,1582.5 2190,1575 v1(2200,1575) ; U10.15@2147.6,1732.5 2224,1732.5 C39.2@2230.32,1738.82
  Top Layer w16: C23.2@1911.5,900 C19.1@2060,900 ; v1(2210,1135) 2212.01,1137.01 U8.9@2212.01,1160 ; v1(2805,1175) R47.2@2838.5,1175 2838.5,1203.5 v1(2840,1205) ; C51.2@2905,1578.5 2933.5,1578.5 v1(2935,1580) ; U12.1@2951.14,925.43 3099.57,925.43 C49.1@3115,910 ; U12.3@2951.14,976.61 2908.39,976.61 2885,1000 v1(2885,1030) 2887.2,1027.8 U12.5@2951.14,1027.8 ; C42.2@2956.5,865 U12.1@2956.5,920.08 ; v1(2960,840) C42.2@2960,868.5 ; v1(3020,1520) C52.2@3053.5,1520 3053.5,1575 C53.2@3050,1578.5 ; C48.2@3116.5,1055 C43.1@3173.5,1055 3173.5,1026.5 v1(3175,1025) ; v1(3250,1320) 3251.5,1318.5 C46.2@3251.5,1290 ; v1(3310,1025) C45.2@3310,1058.5 ; U14.8@3355,1750.39 v1(3355,1770) ; U11.14@3493.39,888.86 3493.39,921.61 3511.77,940 3573.5,940 C47.2@3595,918.5 3596.5,920 v1(3625,920) v1@3630,920 ; C40.1@3595,1126.5 3623.5,1126.5 v1(3625,1125)
  Top Layer w20: C5.1@1668.9,1020 v1(1700,1020) ; C5.1@1676.93,995 v1(1700,995) ; C23.2@1900,911.5 v1(1900,930) ; T1.7@1980.04,620.98 v1(2029.02,620.98) ; T1.5@1992.09,815 v1(2030,815) ; v1(2060,870) C19.1@2060,900 ; v1(2085,870) C19.1@2085,895 ; v1(2155.59,535) C9.2@2186.12,535 ; v1(2155.59,645) C12.1@2186.12,645 ; v1(2160,1010.02) 2192.2,1010.02 2200,1002.22 2200,974.21 C21.2@2237.72,936.5 ; v1(2160,1070.02) 2184.47,1070.02 C16.2@2189.8,1070.02 ; C15.2@2193.5,1011.32 C16.2@2193.5,1071.32 ; U8.15@2212.01,1460 C35.2@2281.5,1460 ; C39.2@2236.5,1745 v1(2260,1745) ; C35.2@2290,1468.5 2355,1468.5 v1(2355,1500) ; U6.2@2345.32,835.87 2345.32,867.4 2347.72,869.8 v1(2347.72,870) ; C36.2@2390,1488.07 v1(2390,1500) ; C36.2@2398.07,1465 v1(2410,1465) ; v1(2405.98,377.52) D2.2@2405.98,408.05 ; D3.1@2410.98,747.52 v1(2441.52,747.52) ; C24.2@2420,1080.3 v1(2420,1111.09) ; C41.2@2650,873.5 v1(2650,900) ; v1(3905,435) C25_CMCh4.1@3939.76,435 3939.76,385.3 U7_CMCh4.5@3918.98,364.51 ; v1(3910,145) C31_CMCh4.2@3944.28,145 ; v1(3910,640) C31_CMCh3.2@3940.25,640 ; v1(3915,1195) C31_CMCh2.2@3945.21,1195 ; v1(3915,1665) C31_CMCh1.2@3945.48,1665 ; U7_CMCh3.5@3918.98,864.51 3918.98,914.21 C25_CMCh3.1@3939.76,935 ; U7_CMCh2.5@3921.2,1413.23 3921.2,1462.93 C25_CMCh2.1@3941.98,1483.72 ; U7_CMCh1.5@3921.2,1886.5 3921.2,1936.2 C25_CMCh1.1@3941.98,1956.99 ; C25_CMCh3.1@3940,935.24 v1(3940,965) ; C25_CMCh1.1@3940,1958.97 v1(3940,1990) ; C25_CMCh2.1@3945,1486.73 v1(3945,1515) ; C26_CMCh4.1@4132.76,435 4202.52,435 D7_CMCh4.2@4222.52,415 ; C26_CMCh3.1@4132.76,935 4202.52,935 D7_CMCh3.2@4222.52,915 ; U7_CMCh4.1@4133.54,214.51 4137.76,210.3 C30_CMCh4.2@4137.76,144.51 4167.76,174.51 D10_CMCh4.2@4217.52,174.51 ; U7_CMCh3.1@4133.54,714.51 4137.76,710.3 C30_CMCh3.2@4137.76,644.51 4167.76,674.51 D10_CMCh3.2@4217.52,674.51 ; v1(4135,115) C30_CMCh4.2@4135,141.76 ; C26_CMCh3.1@4135,937.24 v1(4135,965) ; C26_CMCh2.1@4134.98,1483.72 4204.74,1483.72 D7_CMCh2.2@4224.74,1463.72 ; v1(4135,1990) 4135,1957.01 4204.74,1956.99 D7_CMCh1.2@4224.74,1936.99 ; U7_CMCh2.1@4135.76,1263.23 4139.98,1259.02 4139.98,1193.23 4169.98,1223.23 D10_CMCh2.2@4219.74,1223.23 ; U7_CMCh1.1@4135.76,1736.5 4139.98,1732.29 C30_CMCh1.2@4139.98,1666.5 ; C26_CMCh4.1@4140,442.24 v1(4140,465) ; v1(4140,615) C30_CMCh3.2@4140,642.27 ; v1(4140,1165) C30_CMCh2.2@4140,1193.2 ; C26_CMCh2.1@4140,1488.74 v1(4140,1515) ; v1(4140,1635) C30_CMCh1.2@4140,1666.48 ; D10_CMCh1.2@4219.74,1696.5 4169.98,1696.5 C30_CMCh1.2@4139.98,1666.5 ; C27_CMCh2.2@4485,1472.2 v1(4485,1500) ; v1(4490,115) C29_CMCh4.1@4490,153.74 ; v1(4490,615) C29_CMCh3.1@4490,653.74 ; v1(4490,1165) C29_CMCh2.1@4490,1200.24 ; C27_CMCh4.2@4491.26,415 v1(4535,415) ; v1(4495,1640) C29_CMCh1.1@4495,1675.47 ; C27_CMCh1.2@4495.47,1935 v1(4535,1935) ; C27_CMCh3.2@4496.26,910 v1(4535,910) ; R32_NoCMCh4.1@5185,570 5475.68,570 D12_NoCMCh4.1@5507,601.32 5562.51,545.81 C32_NoCMCh4.2@5632,545.81 v1(5664.19,545.81) ; R32_NoCMCh3.1@5185,940 5475.68,940 D12_NoCMCh3.1@5507,971.32 5562.51,915.81 C32_NoCMCh3.2@5632,915.81 v1(5664.19,915.81) ; R32_NoCMCh2.1@5185,1310 5475.68,1310 D12_NoCMCh2.1@5507,1341.32 5562.51,1285.81 C32_NoCMCh2.2@5632,1285.81 v1(5664.19,1285.81) ; R32_NoCMCh1.1@5185,1690 5475.68,1690 D12_NoCMCh1.1@5507,1721.32 5562.51,1665.81 C32_NoCMCh1.2@5632,1665.81 v1(5664.19,1665.81) ; D8_CMCh4.2@5834.53,592.72 v1(5834.53,619.53) ; v1(5834.53,700.47) D8_CMCh3.2@5834.53,730.51 ; D8_CMCh2.2@5834.53,868.32 v1(5861.68,868.32) ; v1(5834.53,975.47) D8_CMCh1.2@5834.53,1006.11 ; D11_NoCMCh4.2@5834.53,1143.9 v1(5861.1,1143.9) ; D11_NoCMCh3.2@5834.53,1281.69 v1(5863.31,1281.69) ; v1(5834.53,1390.47) D11_NoCMCh2.2@5834.53,1419.49 ; v1(5834.53,1530.47) D11_NoCMCh1.2@5834.53,1557.28
  GND w6: v1(4535,415) v1@4540,415
I2C_A0: R14.2 S1.4 U1.1 U4.1 | length 404.3
  Top Layer w6: U4.1@387.2,556.61 446.12,556.63 U1.1@501.63,501.12 ; S1.4@405,310 391.43,323.57 391.43,442.92 R14.2@421.08,472.57 ; R14.2@425.02,468.64 478.01,468.64 U1.1@501.61,492.24
I2C_A1: R13.2 S1.3 U1.5 U4.2 | length 703.3
  Top Layer w6: R13.2@340.02,476.51 340.02,528.16 330.88,537.29 330.88,564.12 330,565 347.2,582.2 U4.2@377.23,582.2 ; R13.2@350.02,476.51 318.44,444.94 318.44,301.56 360,260 S1.3@405,260 ; U4.2@379.44,580 U4.2@377.23,582.2 ; U1.5@578.4,638.91 578.4,593.4 555.13,570.13 522.63,570.13 510.55,582.2 U4.2@387.2,582.2 U4.2@377.23,582.2
I2C_CLK: J1.19 R16.2 U4.6 | length 2121.3
  Top Layer w6: U4.6@162.8,607.8 119.13,607.8 112.87,601.54 112.87,527.4 137.65,502.62 166.03,502.62 199.28,469.37 R16.2@200.01,468.64 ; R16.2@200.01,476.51 200.01,470.11 168.44,438.54 168.44,380.96 219.7,329.7 254.7,329.7 v1(255,330) ; v1(505,320) 721.1,320 806.1,235 1685,235 1725,195 1725,125 J1.19@1675,75
  Bottom Layer w6: v1(255,330) 265,320 v1(505,320)
I2C_SDA: J1.20 R17.2 U4.5 | length 2001
  Top Layer w6: U4.5@152.81,633.4 119.46,633.4 95,608.94 95,520 125.01,489.98 125.01,470.11 93.44,438.54 93.44,359.34 102.66,350.13 164.78,350.13 203.08,311.83 228.17,311.83 v1(255,285) ; v1(530,285) 730.82,285 789.82,226 795.48,226 800.35,221.13 1628.87,221.13 J1.20@1675,175
  Bottom Layer w6: v1(255,285) v1(530,285)
IN1+IN2: R5.2 R6.2 TP19.1 U10.6 | length 1079.6
  Top Layer w6: TP19.1@1065,1535 1198.7,1668.7 R6.2@1198.7,1768.5 R5.2@1258.7,1768.5 1387.2,1640 1903.35,1640 1908.35,1635 1930.53,1635 U10.6@1933.03,1632.5
IN1+IN2_ISO: U10.11 U12.9 U15.1 U15.5 | length 1189.9
  Top Layer w6: U10.11@2147.6,1632.5 2169.78,1632.5 2180.91,1643.63 2481.37,1643.63 2495,1630 2567.5,1630 ; U15.1@2652.09,1688.74 2583.74,1688.74 2567.5,1672.5 2567.5,1630 ; U12.9@2718.86,1104.57 2718.86,1216.14 2652.09,1282.91 2652.09,1610 2587.5,1610 2567.5,1630
NetC10_1: C10.1 T1.2 U5.10 U5.11 U5.12
NetC10_2: C10.2 U5.13 | length 87.7
  Top Layer w10: U5.13@1494.53,665.12 1543.61,665.12 1561.37,682.87 C10.2@1574.87,682.87
NetC11_1: C11.1 R18.1 | length 72.6
  Top Layer w20: R18.1@2090,582.99 C11.1@2090,655.57
NetC11_2: C11.2 D4.1 T1.6 | length 229.2
  Top Layer w20: T1.6@1980.04,719.02 2179.55,719.02 D4.1@2200.53,740
NetC13_1: C13.1 C14.1 R22.2 T1.1 TP9.1 | length 606
  Top Layer w20: TP9.1@1295,335 1316.5,313.5 1536.57,313.5 C13.1@1655,431.93 ; T1.1@1659.96,522.95 1655,517.99 C13.1@1655,431.93 ; C14.1@1750,431.93 C13.1@1655,431.93
NetC17_1: C17.1 U5.9 | length 276.5
  Top Layer w8: C17.1@1505,778.5 1513.9,769.6 v1(1513.9,725) ; U5.9@1520.12,580.47 1538.43,580.47 v1(1553.9,565) v1@1553.9,567.52
  VDD w8: v1(1513.9,725) 1553.9,685 v1(1553.9,565)
NetC18_1: C18.1 C19.2 D6.1 R25.1 | length 298.9
  Top Layer w20: D6.1@1887.36,1000 1970,1000 C18.1@1980,990 C19.2@2070,990 2106.5,990 R25.1@2160,936.5
NetC20_1: C20.1 C22.2 U5.7 | length 119.4
  Top Layer w8: C22.2@1455.75,443.35 1455.75,498.7 1474.84,517.79 U5.7@1474.84,554.88
NetC20_2: C20.2 R28.2 | length 59.6
  Top Layer w6: R28.2@1518.74,443.35 1517.25,441.85 1517.25,497.2 C20.2@1518.74,498.7
NetC21_1: C21.1 D5.1 J3.3 R25.2 U6.1 | length 610
  Top Layer w6: U6.1@2307.91,835.87 2307.91,830.87 2307.91,827.4 2330.32,805 2460,805 J3.3@2510,855
  Top Layer w10: U6.1@2307.91,835.87 2307.91,887.91 2345,925 D5.1@2345,1020
  Top Layer w20: R25.2@2160,873.5 C21.1@2235.67,873.5 ; C21.1@2234.02,875.16 C21.1@2235.67,873.5 ; C21.1@2237.72,873.5 C21.1@2235.67,873.5 ; U6.1@2307.91,830.87 2278.31,830.87 C21.1@2235.67,873.5
NetC23_1: C23.1 R27.1 | length 63.5
  Top Layer w20: R27.1@1775,900 C23.1@1838.5,900
NetC24_1: C24.1 U6.4 | length 84.8
  Top Layer w12: U6.4@2382.72,944.13 2382.72,972.72 2412.72,1002.72 2412.72,1006.22 C24.1@2420,1013.5
NetC44_1: C44.1 R46.1 TP25.1 U12.7 | length 252.9
  Top Layer w16: U12.7@2951.14,1078.98 2992.48,1078.98 3028.5,1115 3028.5,1256.5 TP25.1@3015,1270
NetC44_2: C44.2 R47.1 U12.8 | length 130.5
  Top Layer w16: R47.1@2901.5,1175 C44.2@2958.5,1175 2951.14,1167.64 U12.8@2951.14,1104.57
NetC45_1: C45.1 TP24.1 U11.8 U13.3 | length 414.6
  Top Layer w6: TP24.1@3290,1420 3295,1415 3295,1135.24 C45.1@3309.37,1120.87
  Top Layer w16: U13.3@3257.4,1120.87 C45.1@3309.37,1120.87 ; C45.1@3310,1121.14 U11.8@3365.43,1121.14
NetC48_1: C48.1 C49.2 U12.6 | length 193.5
  Top Layer w16: U12.6@2951.14,1053.39 3051.89,1053.39 C48.1@3053.5,1055 3115,993.5 C49.2@3115,990
NetC50_2: C50.2 U12.4 | length 88.9
  Top Layer w12: U12.4@2951.14,1002.2 3022.8,1002.2 C50.2@3035,990
NetC53_1: C53.1 R50.2 TP27.1 U14.13 | length 340
  Top Layer w6: v1(2960,1650) 2980,1650 2981.5,1648.5 R50.2@2985,1648.5 ; R50.2@2985,1643.5 3037.01,1643.5 3042.01,1638.5 3050.71,1647.2 U14.13@3123.86,1647.2
  Bottom Layer w6: TP27.1@2900,1795 2955,1740 2960,1735 v1(2960,1650)
NetD1_2: D1.2 R18.2 T1.8 | length 234.9
  Top Layer w20: T1.8@1980.04,522.95 2002.05,522.95 2025,500 R18.2@2090,500 2095,500 2155,440 D1.2@2180.53,440
NetD6_2: D6.2 R27.2 T1.4 | length 224.6
  Top Layer w20: T1.4@1659.96,817.05 1685,842.09 R27.2@1685,910 1685,924.47 D6.2@1760.53,1000
NetD8_CMCh1_1: D8_CMCh1.1 K1_CMCh1.2 | length 2253.8
  Top Layer w6: K1_CMCh1.2@4573.48,2017.22 4630.7,1960 v1(4925,1960) ; v1(5765,1045) 5765,1016.59 D8_CMCh1.1@5775.48,1006.11
  VDD w6: v1(4925,1960) 5065,2100 5550,2100 5775,1875 5775,1055 v1(5765,1045)
NetD8_CMCh2_1: D8_CMCh2.1 K1_CMCh2.2 | length 1658.6
  Top Layer w6: K1_CMCh2.2@4573.48,1543.95 4637.43,1480 4975,1480 5050,1405 v1(5050,1190) ; D8_CMCh2.1@5775.48,868.32 5790,882.84 v1(5790,900)
  Bottom Layer w6: v1(5050,1190) 5050,1170 5140,1080 5610,1080 v1(5790,900)
NetD8_CMCh3_1: D8_CMCh3.1 K1_CMCh3.2 | length 1509.2
  Top Layer w6: K1_CMCh3.2@4571.26,995.24 4631.5,935 5020,935 5050,905 5050,720 5040,710 v1(5040,685) ; v1(5705,725) 5769.96,725 D8_CMCh3.1@5775.48,730.51
  Bottom Layer w6: v1(5040,685) 5040,710 5055,725 v1(5705,725)
NetD8_CMCh4_1: D8_CMCh4.1 K1_CMCh4.2 | length 1300.5
  Top Layer w6: K1_CMCh4.2@4571.26,495.24 4636.5,430 4870,430 v1(4910,470) ; v1(5730,595) 5735,595 5737.28,592.72 D8_CMCh4.1@5775.47,592.72
  Bottom Layer w6: v1(4910,470) 5035,595 v1(5730,595)
NetD11_NoCMCh1_1: D11_NoCMCh1.1 K2_NoCMCh1.2 | length 845
  Top Layer w6: v1(5240,1810) 5250,1800 5270,1800 5275,1795 K2_NoCMCh1.2@5275,1760.24 ; v1(5700,1560) 5772.76,1560 D11_NoCMCh1.1@5775.48,1557.28
  VDD w6: v1(5240,1810) 5250,1800 5680,1800 5700,1780 v1(5700,1560)
NetD11_NoCMCh2_1: D11_NoCMCh2.1 K2_NoCMCh2.2 | length 537.1
  Top Layer w6: K2_NoCMCh2.2@5275,1380.24 5275,1415 5279.49,1419.49 D11_NoCMCh2.1@5775.48,1419.49
NetD11_NoCMCh3_1: D11_NoCMCh3.1 K2_NoCMCh3.2 | length 724.2
  Top Layer w6: K2_NoCMCh3.2@5275,1010.24 5279.76,1015 v1(5300,1015) ; v1(5745,1280) 5773.78,1280 D11_NoCMCh3.1@5775.48,1281.69
  VDD w6: v1(5300,1015) 5345,1060 5675,1060 5695,1080 5695,1270 5705,1280 v1(5745,1280)
NetD11_NoCMCh4_1: D11_NoCMCh4.1 K2_NoCMCh4.2 | length 923.7
  Top Layer w6: K2_NoCMCh4.2@5275,640.24 5275,700 5287.87,712.87 5617.87,712.87 v1(5740,835) ; v1(5745,1145) 5774.38,1145 D11_NoCMCh4.1@5775.48,1143.9
  VDD w6: v1(5740,835) 5740,1140 v1(5745,1145)
NetJ2_15: J2.15 R5.1 | length 275.7
  Top Layer w6: R5.1@1258.7,1831.5 1342.2,1915 1415,1915 J2.15@1475,1975
NetJ2_16: J2.16 R6.1 | length 430.3
  Top Layer w6: R6.1@1198.7,1831.5 1198.7,1863.7 1210,1875 1275,1875 1333.61,1933.61 1392.14,1933.61 1416.39,1957.86 1416.39,2016.39 J2.16@1475,2075
NetJ2_17: J2.17 R7.1 | length 235.8
  Top Layer w6: R7.1@1398.68,1831.5 1454.44,1887.25 1465.4,1887.25 1553.15,1975 J2.17@1575,1975
NetJ2_18: J2.18 R8.1 | length 406.8
  Top Layer w6: R8.1@1338.68,1831.5 1338.68,1891.86 1347.95,1901.13 1459.65,1901.13 1516.39,1957.86 1516.39,2016.39 J2.18@1575,2075
NetJ2_27: J2.27 R9.1 | length 594.4
  Top Layer w6: R9.1@1540,1831.5 1631.51,1923.01 2023.01,1923.01 J2.27@2075,1975
NetJ2_28: J2.28 R10.1 | length 718.4
  Top Layer w6: R10.1@1480,1831.5 1582.12,1933.61 1592.14,1933.61 1620,1961.47 1620,2000 1645,2025 2025,2025 J2.28@2075,2075
NetJ2_29: J2.29 R11.1 | length 554.4
  Top Layer w6: R11.1@1680,1831.5 1743.76,1895.26 2095.26,1895.26 J2.29@2175,1975
NetJ2_30: J2.30 R12.1 | length 690.1
  Top Layer w6: R12.1@1620,1831.5 1697.64,1909.13 2067.66,1909.13 2125,1966.47 2125,2025 J2.30@2175,2075
NetJ3_2: J3.2 U6.3 | length 193.9
  Top Layer w6: U6.3@2382.72,837.4 U6.3@2382.72,835.87 2382.72,862.72 2475,955 J3.2@2510,955
NetK1_CMCh1_1: K1_CMCh1.1 R29_CMCh1.1 | length 105.6
  Top Layer w6: K1_CMCh1.1@4671.26,2020.24 4748.27,2020.24 R29_CMCh1.1@4768.5,2000
NetK1_CMCh1_4: K1_CMCh1.4 R30_CMCh1.2 | length 93.9
  Top Layer w20: R30_CMCh1.2@4663.48,1706.99 4673.48,1716.99 K1_CMCh1.4@4673.48,1796.75
NetK1_CMCh2_1: K1_CMCh2.1 R29_CMCh2.1 | length 112.7
  Top Layer w6: K1_CMCh2.1@4671.26,1545.24 4748.27,1545.24 R29_CMCh2.1@4773.5,1520
NetK1_CMCh2_4: K1_CMCh2.4 R30_CMCh2.2 | length 93.9
  Top Layer w20: R30_CMCh2.2@4663.48,1233.72 4673.48,1243.72 K1_CMCh2.4@4673.48,1323.48
NetK1_CMCh3_1: K1_CMCh3.1 R29_CMCh3.1 | length 112.7
  Top Layer w6: K1_CMCh3.1@4671.26,995.24 4748.27,995.24 R29_CMCh3.1@4773.5,970
NetK1_CMCh3_4: K1_CMCh3.4 R30_CMCh3.2 | length 93.9
  Top Layer w20: R30_CMCh3.2@4661.26,685 4671.26,695 K1_CMCh3.4@4671.26,774.76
